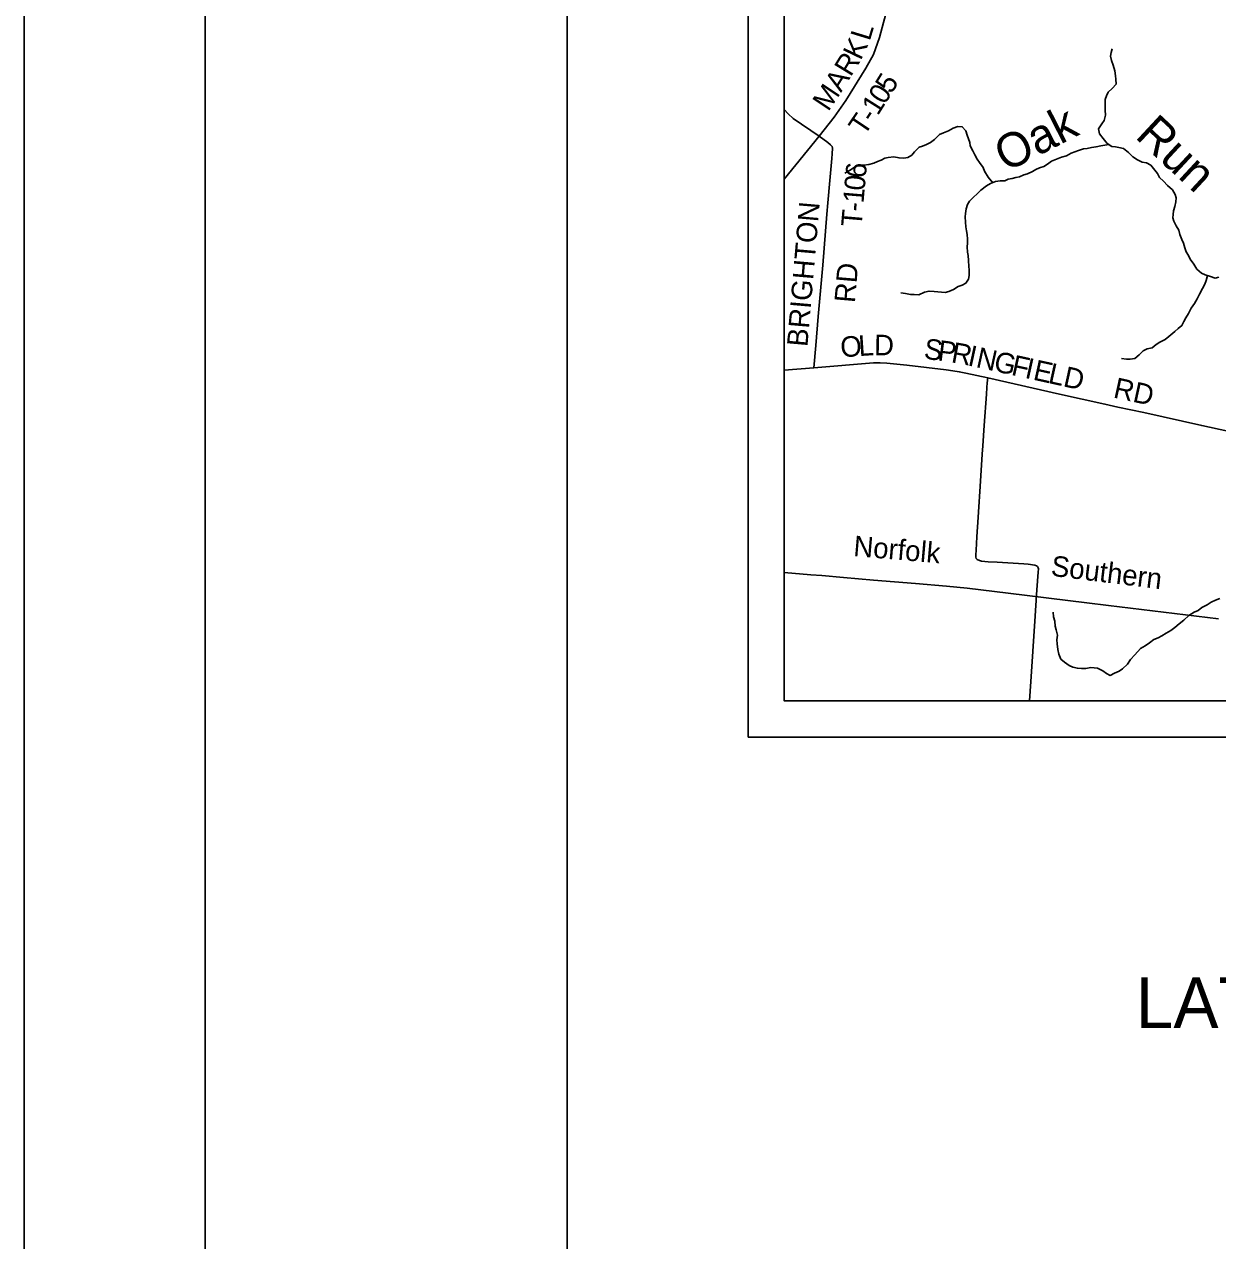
# Model space of a CAD drawing. Extents: x 0 to 36.5, y 0 to 25.3.
# Drawn here: x 0 to 3.297, y 12.609 to 15.97 of the extents above; entities that cross this region are included whole.
import ezdxf

# ---------------------------------------------------------------- set-up
doc = ezdxf.new("R2010")
doc.units = 0
for name, color, linetype in [('DV_X_Township_Line', 7, 'Continuous'), ('GM_X_County_Road', 7, 'Continuous'), ('GM_X_County_Road_Text', 7, 'Continuous'), ('GM_X_Minor_River', 7, 'Continuous'), ('GM_X_Minor_River_Text', 7, 'Continuous'), ('GM_X_Rail_Line', 7, 'Continuous'), ('GM_X_Rail_Line_Text', 7, 'Continuous'), ('GM_X_Township_Road', 7, 'Continuous'), ('GM_X_Township_Road_Text', 7, 'Continuous'), ('SH_Border', 7, 'Continuous'), ('SH_Cut_Line', 7, 'Continuous'), ('SH_Data', 7, 'Continuous'), ('SH_Text', 7, 'Continuous')]:
    doc.layers.add(name, color=color, linetype=linetype)

msp = doc.modelspace()

# ---------------------------------------------------------------- linework, layer by layer
at = {"layer": 'DV_X_Township_Line'}
msp.add_lwpolyline([(2.1, 16.2788), (2.1, 14.1), (8.9, 14.1), (8.9, 14.8674), (8.5228, 15.0526), (8.0723, 15.2737), (7.8139, 15.4027), (7.7814, 15.4189), (7.7552, 15.432), (7.703, 15.458), (6.8419, 15.8878), (6.6079, 15.9978), (5.1383, 16.6527), (4.8891, 16.7511), (4.0938, 16.595), (2.4938, 16.3413), (2.1039, 16.2931)], close=True, dxfattribs=at)
at = {"layer": 'GM_X_County_Road'}
msp.add_line((2.1, 15.0136), (2.1813, 15.0201), dxfattribs=at)
for points in [[(2.1813, 15.0201), (2.3467, 15.034), (2.3651, 15.0344), (2.3835, 15.0331), (2.4381, 15.0275), (2.5472, 15.015), (2.5654, 15.0125), (2.5835, 15.0095), (2.6015, 15.0057), (2.6624, 14.9924)], [(2.7778, 14.1), (2.781, 14.1535), (2.792, 14.3203), (2.798, 14.4066), (2.8019, 14.456), (2.802, 14.4648), (2.8013, 14.4679), (2.8, 14.4714), (2.7964, 14.4737), (2.7921, 14.4754), (2.7739, 14.4778), (2.7616, 14.4787), (2.6877, 14.4834), (2.663, 14.4846), (2.6446, 14.4864), (2.639, 14.4877), (2.6327, 14.491), (2.6305, 14.4937), (2.6295, 14.4974), (2.6291, 14.5039), (2.63, 14.5165), (2.6308, 14.5349), (2.6323, 14.5534), (2.6355, 14.6078), (2.6421, 14.7076), (2.6471, 14.7815), (2.6489, 14.8047), (2.6524, 14.8607), (2.6586, 14.948), (2.6597, 14.9665), (2.6607, 14.9788), (2.6624, 14.9924)], [(2.6624, 14.9924), (2.8607, 14.9479), (2.9859, 14.9201), (3.0216, 14.9117), (3.093, 14.8968), (3.2535, 14.8609), (3.3251, 14.8458), (3.4146, 14.8282), (3.4505, 14.8223), (3.6326, 14.7957), (3.7599, 14.7792), (3.8775, 14.7645)]]:
    msp.add_lwpolyline(points, dxfattribs=at)
at = {"layer": 'GM_X_Minor_River'}
for points in [[(3.2625, 15.2778), (3.2527, 15.2821), (3.2402, 15.2932), (3.232, 15.3073), (3.2215, 15.3207), (3.217, 15.3313), (3.2107, 15.3409), (3.2066, 15.3519), (3.2033, 15.3652), (3.1981, 15.3755), (3.1929, 15.3892), (3.19, 15.4006), (3.1832, 15.4128), (3.1761, 15.4254), (3.1736, 15.4349), (3.1744, 15.4444), (3.1756, 15.4543), (3.1792, 15.466), (3.1823, 15.4793), (3.1828, 15.4899), (3.1802, 15.4994), (3.1724, 15.512), (3.1588, 15.5243), (3.1479, 15.5365), (3.137, 15.5468), (3.131, 15.5571), (3.1235, 15.5671), (3.1126, 15.5801), (3.1006, 15.587), (3.0884, 15.589), (3.0756, 15.5948), (3.0628, 15.6037), (3.0507, 15.6159), (3.0375, 15.627), (3.0243, 15.6294), (3.0148, 15.631), (3.005, 15.6322), (2.9925, 15.6403), (2.9809, 15.6541), (2.9711, 15.6671), (2.9686, 15.6807), (2.9771, 15.6943), (2.984, 15.7042), (2.9875, 15.7186), (2.9869, 15.7322), (2.9866, 15.7467), (2.9864, 15.7618), (2.9906, 15.7721), (2.9945, 15.7819), (3.006, 15.7924), (3.0171, 15.8045), (3.0165, 15.8178), (3.0154, 15.8273), (3.0136, 15.8413), (3.0088, 15.8569), (3.004, 15.8695), (3.0015, 15.8821), (3.0027, 15.8915), (3.0055, 15.9018)], [(2.6761, 15.5321), (2.6635, 15.5474), (2.653, 15.5638), (2.6493, 15.5741), (2.6396, 15.5875), (2.6332, 15.597), (2.6265, 15.6088), (2.6213, 15.6203), (2.6138, 15.6336), (2.6124, 15.6431), (2.6087, 15.6534), (2.6057, 15.6633), (2.602, 15.6751), (2.5915, 15.6866), (2.5794, 15.6871), (2.5664, 15.683), (2.5534, 15.6751), (2.5394, 15.6696), (2.5291, 15.6655), (2.5153, 15.6515), (2.5038, 15.6429), (2.4932, 15.6377), (2.4817, 15.6328), (2.4722, 15.6303), (2.4596, 15.6175), (2.4519, 15.6077), (2.4416, 15.6013), (2.4302, 15.5995), (2.417, 15.6004), (2.4026, 15.6039), (2.3874, 15.6017), (2.3779, 15.6003), (2.3672, 15.5943), (2.3577, 15.5902), (2.3478, 15.5858), (2.3333, 15.5821), (2.3196, 15.5807), (2.3056, 15.5816), (2.293, 15.5737), (2.2797, 15.5662), (2.2675, 15.558)], [(2.997, 15.6374), (2.9742, 15.6336), (2.9613, 15.6315), (2.9492, 15.6293), (2.937, 15.6267), (2.9267, 15.6261), (2.9127, 15.6212), (2.9028, 15.6171), (2.8929, 15.6138), (2.8795, 15.6067), (2.8658, 15.6023), (2.8521, 15.5974), (2.8384, 15.5915), (2.8273, 15.5836), (2.817, 15.5772), (2.8049, 15.5728), (2.7953, 15.5687), (2.7858, 15.5631), (2.7721, 15.5564), (2.7614, 15.5538), (2.7496, 15.5486), (2.7401, 15.5464), (2.7295, 15.5438), (2.7188, 15.5416), (2.7093, 15.5375), (2.6964, 15.5369), (2.6831, 15.5351), (2.6698, 15.5295), (2.6583, 15.5235), (2.6434, 15.5111), (2.6335, 15.5025), (2.622, 15.4908), (2.6117, 15.4814), (2.6059, 15.4716), (2.6024, 15.4598), (2.6008, 15.4473), (2.5999, 15.4378), (2.6005, 15.4234), (2.6019, 15.4105), (2.6037, 15.3995), (2.6052, 15.3888), (2.6058, 15.3763), (2.6061, 15.3653), (2.6056, 15.355), (2.6066, 15.3402), (2.6077, 15.3307), (2.6091, 15.3167), (2.6101, 15.3007), (2.6111, 15.2912), (2.611, 15.276), (2.6086, 15.2651), (2.6013, 15.2545), (2.5918, 15.2489), (2.5808, 15.2455), (2.5674, 15.2369), (2.5545, 15.2313), (2.5442, 15.2284), (2.5339, 15.2292), (2.5241, 15.2301), (2.5142, 15.2313), (2.4998, 15.2326), (2.4869, 15.2296), (2.4717, 15.2218), (2.4584, 15.223), (2.4489, 15.2235), (2.4353, 15.2255), (2.4224, 15.2275)], [(3.2694, 15.2757), (3.2654, 15.2622), (3.2619, 15.252), (3.2557, 15.2395), (3.2468, 15.2244), (3.2406, 15.2112), (3.2337, 15.1987), (3.2245, 15.1851), (3.2164, 15.1708), (3.2098, 15.159), (3.204, 15.1481), (3.1986, 15.1371), (3.1883, 15.1288), (3.1788, 15.1206), (3.1623, 15.1067), (3.1524, 15.0988), (3.1379, 15.0913), (3.1276, 15.0849), (3.1169, 15.0759), (3.1025, 15.0726), (3.0918, 15.067), (3.0803, 15.0561), (3.0685, 15.0467), (3.0552, 15.0442), (3.0457, 15.0446), (3.0316, 15.0463)], [(3.3011, 15.2714), (3.2909, 15.2684), (3.2776, 15.2731), (3.2625, 15.2778)], [(3.3035, 14.3831), (3.2917, 14.3783), (3.2791, 14.3727), (3.2681, 14.366), (3.2536, 14.3585), (3.244, 14.3502), (3.2322, 14.345), (3.2181, 14.3364), (3.2043, 14.3236), (3.1906, 14.3135), (3.1787, 14.3033), (3.1684, 14.2943), (3.1547, 14.2872), (3.1436, 14.2801), (3.133, 14.2748), (3.1208, 14.2696), (3.1093, 14.261), (3.0975, 14.2524), (3.0841, 14.2449), (3.0688, 14.2272), (3.0562, 14.2147), (3.0485, 14.2019), (3.0343, 14.1891), (3.0248, 14.1827), (3.0126, 14.1771), (3, 14.1704), (2.9902, 14.1754), (2.9804, 14.1835), (2.9656, 14.1904), (2.9562, 14.1917), (2.9467, 14.1921), (2.933, 14.19), (2.9212, 14.1893), (2.9099, 14.1905), (2.8974, 14.1937), (2.8868, 14.1983), (2.874, 14.2068), (2.8638, 14.2156), (2.8582, 14.2293), (2.8557, 14.2422), (2.8539, 14.2582), (2.8533, 14.2684), (2.8553, 14.2813), (2.8509, 14.2962), (2.8483, 14.3068), (2.8473, 14.3201), (2.844, 14.3327), (2.8429, 14.3452)]]:
    msp.add_lwpolyline(points, dxfattribs=at)
at = {"layer": 'GM_X_Rail_Line'}
msp.add_lwpolyline([(2.1, 14.4553), (2.1735, 14.4489), (2.2036, 14.4463), (2.2632, 14.4411), (2.3463, 14.4341), (2.4625, 14.4244), (2.5483, 14.4167), (2.6055, 14.4112), (2.7185, 14.3977), (2.9357, 14.371), (2.9959, 14.3635), (3.2993, 14.3271)], dxfattribs=at)
at = {"layer": 'GM_X_Township_Road'}
msp.add_line((2.1, 15.5418), (2.1961, 15.6605), dxfattribs=at)
for points in [[(2.1961, 15.6605), (2.2376, 15.7131), (2.2696, 15.7589), (2.3252, 15.8486), (2.3463, 15.8865), (2.3626, 15.9333), (2.3881, 16.0266), (2.4061, 16.1141), (2.4156, 16.1754), (2.4201, 16.1926), (2.4502, 16.2815), (2.4585, 16.2981), (2.4693, 16.3132), (2.494, 16.3408)], [(2.1961, 15.6605), (2.1247, 15.7098), (2.1107, 15.7224), (2.1, 15.7347)], [(2.1813, 15.0201), (2.1868, 15.082), (2.1933, 15.1622), (2.2063, 15.3038), (2.2179, 15.4455), (2.2206, 15.4763), (2.2255, 15.5378), (2.2316, 15.5991), (2.2326, 15.6114), (2.2331, 15.6272), (2.232, 15.6323), (2.2278, 15.6371), (2.2207, 15.6435), (2.1961, 15.6605)]]:
    msp.add_lwpolyline(points, dxfattribs=at)
at = {"layer": 'SH_Border'}
for points in [[(0.5, 21.5), (1.5, 21.5), (1.5, 0.5), (0.5, 0.5)], [(1.5, 21.5), (33.5, 21.5), (33.5, 0.5), (1.5, 0.5)]]:
    msp.add_lwpolyline(points, close=True, dxfattribs=at)
at = {"layer": 'SH_Cut_Line'}
msp.add_lwpolyline([(0, 0), (34, 0), (34, 22), (0, 22)], close=True, dxfattribs=at)
msp.add_lwpolyline([(4.4591, 20.9), (3.3366, 20.9), (3.2612, 20.6041), (2.8463, 19.037), (2.6265, 18.2595), (2.5271, 17.8912), (2.5226, 17.8751), (2.5165, 17.8524), (2.5144, 17.8445), (2.4192, 17.4891), (2.3437, 17.2326), (2.3403, 17.2198), (2.1039, 16.2931), (2.1, 16.2788), (2.1, 14.1), (8.9, 14.1), (8.9, 20.9), (6.1845, 20.9)], dxfattribs=at)
at = {"layer": 'SH_Data'}
for p, q in [((2, 21), (2, 14)), ((2.1, 20.9), (2.1, 14.1)), ((2.1, 14.1), (8.9, 14.1)), ((2.1, 14.1), (2.1, 14.1)), ((2, 14), (9, 14))]:
    msp.add_line(p, q, dxfattribs=at)

# ---------------------------------------------------------------- texts
at = {"layer": 'GM_X_County_Road_Text'}
for s, height, rotation, p in [('O', 0.0568, 3.981, (2.2567, 15.0493)), ('L', 0.0568, 3.7955, (2.3065, 15.0528)), ('D', 0.0568, 358.8634, (2.3476, 15.0556)), ('S', 0.0568, 352.6628, (2.4837, 15.0459)), ('P', 0.0568, 352.5143, (2.5217, 15.041)), ('R', 0.0568, 349.5964, (2.559, 15.0361)), ('I', 0.0568, 347.6566, (2.6044, 15.0278)), ('N', 0.0568, 347.5984, (2.6272, 15.0228)), ('G', 0.0568, 347.587, (2.676, 15.0121)), ('F', 0.0568, 347.5921, (2.7248, 15.0013)), ('I', 0.0568, 347.5847, (2.7623, 14.9931)), ('E', 0.0568, 347.5888, (2.785, 14.9881)), ('L', 0.0568, 347.5907, (2.8266, 14.979)), ('D', 0.0568, 347.5886, (2.8681, 14.9698)), ('RD', 0.05682, 347.6261, (3.0066, 14.9389))]:
    msp.add_text(s, height=height, rotation=rotation, dxfattribs=at).set_placement(p)
at = {"layer": 'GM_X_Minor_River_Text'}
for s, rotation, p in [('Oak', 27.0872, (2.7122, 15.5601)), ('Run', 317.0931, (3.0666, 15.6578))]:
    msp.add_text(s, height=0.09469, rotation=rotation, dxfattribs=at).set_placement(p)
at = {"layer": 'GM_X_Rail_Line_Text'}
for s, rotation, p in [('Norfolk', 355.1289, (2.2895, 14.5006)), ('Southern', 352.9993, (2.8348, 14.4461))]:
    msp.add_text(s, height=0.05663, rotation=rotation, dxfattribs=at).set_placement(p)
at = {"layer": 'GM_X_Township_Road_Text'}
for s, height, rotation, p in [('K', 0.0568, 64.3253, (2.3108, 15.8679)), ('L', 0.0568, 72.9726, (2.3358, 15.9217)), ('R', 0.0568, 58.5575, (2.2834, 15.8226)), ('A', 0.0568, 58.0036, (2.2566, 15.7797)), ('5', 0.0568, 58.1215, (2.3957, 15.7752)), ('M', 0.0568, 56.3329, (2.2215, 15.7268)), ('0', 0.0568, 58.031, (2.3771, 15.7454)), ('1', 0.0568, 57.6628, (2.3582, 15.7155)), ('T', 0.0568, 56.1186, (2.3209, 15.6592)), ('-', 0.0568, 57.2464, (2.3453, 15.6955)), ('6', 0.0568, 84.555, (2.3248, 15.543)), ('0', 0.0568, 84.8085, (2.3217, 15.5085)), ('1', 0.0568, 85.2524, (2.3188, 15.474)), ('BRIGHTON', 0.05682, 85.0813, (2.1637, 15.0773)), ('-', 0.0568, 85.2607, (2.3169, 15.451)), ('T', 0.0568, 85.1519, (2.3133, 15.4086)), ('RD', 0.05682, 85.0717, (2.2949, 15.1987))]:
    msp.add_text(s, height=height, rotation=rotation, dxfattribs=at).set_placement(p)
at = {"layer": 'SH_Text'}
msp.add_text('LATITUDE:  39°56\'24"     LONGITUDE:  83°29\'52"', height=0.14, dxfattribs=at).set_placement((3.071, 13.1959))

doc.saveas('drawing.dxf')
